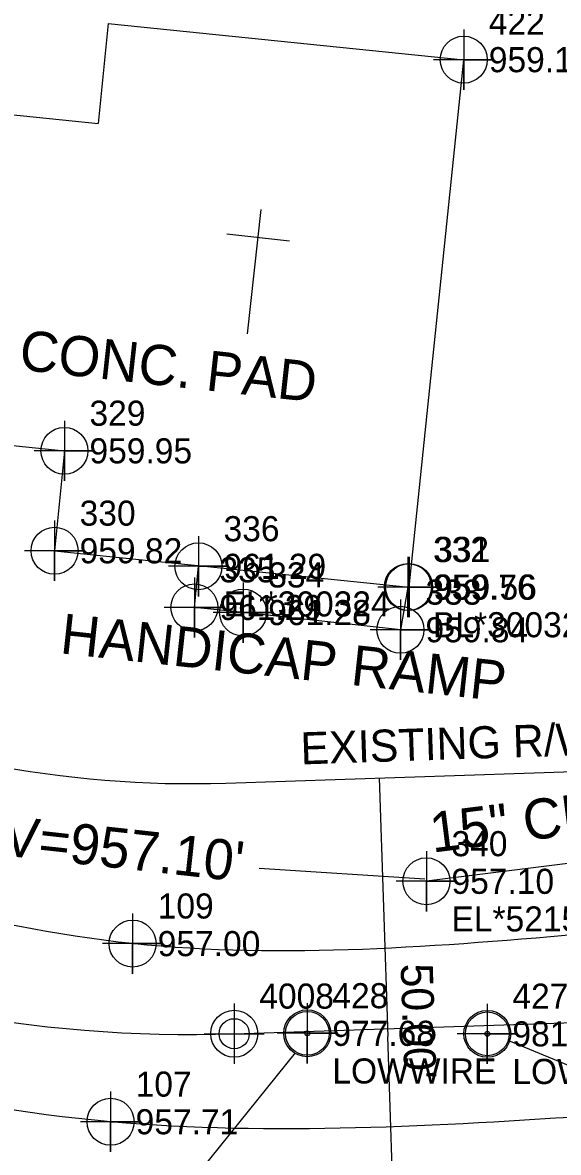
# Model space of a CAD drawing. Extents: x 1150279 to 1151282, y 655434 to 657999.
# Drawn here: x 1150999.3 to 1151052.7, y 657055.2 to 657167.8 of the extents above; entities that cross this region are included whole.
import ezdxf

# ---------------------------------------------------------------- set-up
doc = ezdxf.new("R2010")
doc.units = 0
for name, color, linetype in [('COGO Default Chain', 7, 'Continuous'), ('COGO Default Curve', 7, 'Continuous'), ('Cogo Default Point CELL', 7, 'Continuous'), ('COGO Default Point Number', 7, 'Continuous'), ('Default Symbol CELL', 7, 'Continuous'), ('Default Symbol Cogo Comment', 7, 'Continuous'), ('Default Symbol Cogo Elevation', 7, 'Continuous'), ('Default Symbol Cogo Number', 7, 'Continuous'), ('Exist Building', 7, 'Continuous'), ('Exist Building Cogo Elevation', 7, 'Continuous'), ('Exist Building Cogo Number', 7, 'Continuous'), ('Exist Building Cogo Point CELL', 7, 'Continuous'), ('Exist Horizontal Alignment', 7, 'Continuous'), ('Exist Horizontal Alignment Station Label', 7, 'Continuous'), ('Exist Other Culture Church or Cemetery CELL', 7, 'Continuous'), ('Exist Right of Way Line', 7, 'Continuous'), ('Exist Right of Way Line Text', 7, 'Continuous'), ('Exist Right of Way Width CELL', 7, 'Continuous'), ('Exist Roads EOP', 7, 'Continuous'), ('Exist Roads EOP Cogo Elevation', 7, 'Continuous'), ('Exist Roads EOP Cogo Number', 7, 'Continuous'), ('Exist Roads EOP Cogo Point CELL', 7, 'Continuous'), ('Exist Roads EOP Other', 7, 'Continuous'), ('Exist Roads EOP Other Cogo Comment', 7, 'Continuous'), ('Exist Roads EOP Other Cogo Elevation', 7, 'Continuous'), ('Exist Roads EOP Other Cogo Number', 7, 'Continuous'), ('Exist Roads EOP Other Cogo Point CELL', 7, 'Continuous'), ('Exist Roads EOP Other Text', 7, 'Continuous'), ('Exist Roads EOP Text', 7, 'Continuous'), ('Exist Structure Minor Pipes CMP 15 Inch', 7, 'Continuous'), ('Exist Structure Minor Pipes CMP 15 Inch Cogo Comment', 7, 'Continuous'), ('Exist Structure Minor Pipes CMP 15 Inch Cogo Elevation', 7, 'Continuous'), ('Exist Structure Minor Pipes CMP 15 Inch Cogo Number', 7, 'Continuous'), ('Exist Structure Minor Pipes CMP 15 Inch Cogo Point CELL', 7, 'Continuous'), ('Exist Structure Minor Pipes CMP 15 Inch Leader', 7, 'Continuous'), ('Exist Structure Minor Pipes CMP 15 Inch Text', 7, 'Continuous'), ('Exist Utilities Other Located Object CELL', 7, 'Continuous'), ('Exist Utilities Other Located Object Leader', 7, 'Continuous')]:
    doc.layers.add(name, color=color, linetype=linetype)

msp = doc.modelspace()

# ---------------------------------------------------------------- linework, layer by layer
at = {"layer": 'COGO Default Chain'}
msp.add_line((1151020.37, 657067.07), (1151060.05, 657068.39), dxfattribs=at)
msp.add_arc((1151016.01, 657196.99), 130, 245.6804, 271.9187, dxfattribs=at)
at = {"layer": 'COGO Default Curve'}
msp.add_arc((1151016.01, 657196.99), 130, 245.6804, 271.9187, dxfattribs=at)
at = {"layer": 'Cogo Default Point CELL'}
for points in [[(1151020.37, 657070.07), (1151020.37, 657067.07)], [(1151020.37, 657070.07), (1151020.37, 657067.07)], [(1151017.37, 657067.07), (1151020.37, 657067.07)], [(1151017.37, 657067.07), (1151020.37, 657067.07)], [(1151020.37, 657067.07), (1151023.37, 657067.07)], [(1151020.37, 657067.07), (1151020.37, 657064.07)], [(1151020.37, 657067.07), (1151023.37, 657067.07)], [(1151020.37, 657067.07), (1151020.37, 657064.07)]]:
    msp.add_lwpolyline(points, dxfattribs=at)
msp.add_circle((1151020.37, 657067.07), 2.34, dxfattribs=at)
msp.add_circle((1151020.37, 657067.07), 2.34, dxfattribs=at)
at = {"layer": 'Default Symbol CELL'}
for points in [[(1151027.65, 657070.11), (1151027.65, 657064.11), (1151027.65, 657067.11), (1151030.65, 657067.11), (1151024.65, 657067.11)], [(1151045.59, 657070.06), (1151045.59, 657064.06), (1151045.59, 657067.06), (1151048.59, 657067.06), (1151042.59, 657067.06)]]:
    msp.add_lwpolyline(points, dxfattribs=at)
for centre in [(1151027.65, 657067.11), (1151045.59, 657067.06)]:
    msp.add_circle(centre, 2.34, dxfattribs=at)
at = {"layer": 'Exist Building'}
for p, q in [((1151007.8, 657167.75), (1151006.82, 657157.78)), ((1151007.8, 657167.75), (1151043.24, 657164.12)), ((1150963.17, 657162.3), (1151006.82, 657157.78))]:
    msp.add_line(p, q, dxfattribs=at)
msp.add_lwpolyline([(1150963.17, 657162.3), (1150962, 657151.2), (1150955.74, 657152.17), (1150954.56, 657141.15), (1150960.94, 657140.6), (1150959.8, 657129.69), (1151003.45, 657125.16), (1151002.47, 657115.2), (1151037.8, 657111.58), (1151043.24, 657164.12)], dxfattribs=at)
at = {"layer": 'Exist Building Cogo Point CELL'}
for points in [[(1151043.24, 657167.14), (1151043.24, 657161.14), (1151043.24, 657164.14), (1151046.24, 657164.14), (1151040.24, 657164.14)], [(1151003.45, 657128.16), (1151003.45, 657122.16), (1151003.45, 657125.16), (1151006.45, 657125.16), (1151000.45, 657125.16)], [(1151002.47, 657118.2), (1151002.47, 657112.2), (1151002.47, 657115.2), (1151005.47, 657115.2), (1150999.47, 657115.2)], [(1151037.8, 657114.58), (1151037.8, 657108.58), (1151037.8, 657111.58), (1151040.8, 657111.58), (1151034.8, 657111.58)]]:
    msp.add_lwpolyline(points, dxfattribs=at)
for centre in [(1151043.24, 657164.14), (1151003.45, 657125.16), (1151002.47, 657115.2), (1151037.8, 657111.58)]:
    msp.add_circle(centre, 2.34, dxfattribs=at)
at = {"layer": 'Exist Horizontal Alignment'}
msp.add_line((1151020.37, 657067.07), (1151060.05, 657068.39), dxfattribs=at)
msp.add_arc((1151016.01, 657196.99), 130, 245.6804, 271.9187, dxfattribs=at)
at = {"layer": 'Exist Horizontal Alignment Station Label'}
msp.add_circle((1151020.37, 657067.07), 1.5, dxfattribs=at)
at = {"layer": 'Exist Other Culture Church or Cemetery CELL'}
for p, q in [((1151021.68, 657136.83), (1151023.05, 657149.22)), ((1151019.63, 657146.78), (1151025.87, 657146.09)), ((1151022.37, 657143.04), (1151022.37, 657143.04))]:
    msp.add_line(p, q, dxfattribs=at)
at = {"layer": 'Exist Right of Way Line'}
msp.add_line((1151019.53, 657092.05), (1151059.22, 657093.38), dxfattribs=at)
for radius in [105, 155]:
    msp.add_arc((1151016.01, 657196.99), radius, 245.6804, 271.9187, dxfattribs=at)
at = {"layer": 'Exist Right of Way Width CELL'}
for p in [(1151034.81, 657092.56), (1151036.48, 657042.59)]:
    msp.add_line(p, (1151035.67, 657066.81), dxfattribs=at)
at = {"layer": 'Exist Roads EOP'}
for points in [[(1151056.23, 657077.09), (1151010.25, 657076.05), (1150965.32, 657087.79), (1150920.52, 657109.03), (1150919.16, 657109.82)], [(1151056.97, 657058.93), (1151008.05, 657058.3), (1150957.78, 657070.1), (1150911.09, 657090.11), (1150910.09, 657090.54)]]:
    msp.add_spline(points, degree=3, dxfattribs=at)
at = {"layer": 'Exist Roads EOP Cogo Point CELL'}
for points in [[(1151010.25, 657079.05), (1151010.25, 657073.05), (1151010.25, 657076.05), (1151013.25, 657076.05), (1151007.25, 657076.05)], [(1151008.05, 657061.3), (1151008.05, 657055.3), (1151008.05, 657058.3), (1151011.05, 657058.3), (1151005.05, 657058.3)]]:
    msp.add_lwpolyline(points, dxfattribs=at)
for centre in [(1151010.25, 657076.05), (1151008.05, 657058.3)]:
    msp.add_circle(centre, 2.34, dxfattribs=at)
at = {"layer": 'Exist Roads EOP Other'}
msp.add_lwpolyline([(1151037.68, 657111.58), (1151036.93, 657107.33), (1151021.26, 657109.04), (1151016.4, 657109.55), (1151016.81, 657113.65)], dxfattribs=at)
at = {"layer": 'Exist Roads EOP Other Cogo Point CELL'}
for points in [[(1151016.81, 657116.65), (1151016.81, 657110.65), (1151016.81, 657113.65), (1151019.81, 657113.65), (1151013.81, 657113.65)], [(1151037.68, 657114.58), (1151037.68, 657108.58), (1151037.68, 657111.58), (1151040.68, 657111.58), (1151034.68, 657111.58)], [(1151016.4, 657112.55), (1151016.4, 657106.55), (1151016.4, 657109.55), (1151019.4, 657109.55), (1151013.4, 657109.55)], [(1151021.26, 657112.04), (1151021.26, 657106.04), (1151021.26, 657109.04), (1151024.26, 657109.04), (1151018.26, 657109.04)], [(1151036.93, 657110.33), (1151036.93, 657104.33), (1151036.93, 657107.33), (1151039.93, 657107.33), (1151033.93, 657107.33)]]:
    msp.add_lwpolyline(points, dxfattribs=at)
for centre in [(1151016.81, 657113.65), (1151037.68, 657111.58), (1151016.4, 657109.55), (1151021.26, 657109.04), (1151036.93, 657107.33)]:
    msp.add_circle(centre, 2.34, dxfattribs=at)
at = {"layer": 'Exist Structure Minor Pipes CMP 15 Inch'}
msp.add_line((1151059.72, 657084.82), (1151039.52, 657082.26), dxfattribs=at)
at = {"layer": 'Exist Structure Minor Pipes CMP 15 Inch Cogo Point CELL'}
msp.add_lwpolyline([(1151039.52, 657085.26), (1151039.52, 657079.26), (1151039.52, 657082.26), (1151042.52, 657082.26), (1151036.52, 657082.26)], dxfattribs=at)
msp.add_circle((1151039.52, 657082.26), 2.34, dxfattribs=at)
at = {"layer": 'Exist Structure Minor Pipes CMP 15 Inch Leader'}
msp.add_line((1151039.38, 657082.47), (1151022.85, 657083.53), dxfattribs=at)
at = {"layer": 'Exist Utilities Other Located Object CELL'}
for centre, radius in [((1151027.65, 657067.11), 2.18), ((1151045.59, 657067.06), 2.18), ((1151027.65, 657067.11), 0.24), ((1151045.59, 657067.06), 0.24)]:
    msp.add_circle(centre, radius, dxfattribs=at)
at = {"layer": 'Exist Utilities Other Located Object Leader'}
for points in [[(1151047.69, 657066.38), (1151069.32, 657057.45), (1151082.27, 657056.02)], [(1151026.43, 657065.18), (1151001.23, 657033.86), (1150989.95, 657035.11)]]:
    msp.add_lwpolyline(points, dxfattribs=at)

# ---------------------------------------------------------------- texts
at = {"layer": 'COGO Default Point Number'}
msp.add_text('4008', height=2.5, dxfattribs=at).set_placement((1151022.87, 657069.57))
at = {"layer": 'Default Symbol Cogo Comment'}
for p in [(1151030.15, 657062.11), (1151048.09, 657062.06)]:
    msp.add_text('LOWWIRE', height=2.5, dxfattribs=at).set_placement(p)
at = {"layer": 'Default Symbol Cogo Elevation'}
for s, p in [('977.68', (1151030.15, 657065.86)), ('981.38', (1151048.09, 657065.81))]:
    msp.add_text(s, height=2.5, dxfattribs=at).set_placement(p)
at = {"layer": 'Default Symbol Cogo Number'}
for s, p in [('428', (1151030.15, 657069.61)), ('427', (1151048.09, 657069.56))]:
    msp.add_text(s, height=2.5, dxfattribs=at).set_placement(p)
at = {"layer": 'Exist Building Cogo Elevation'}
for s, p in [('959.11', (1151045.74, 657162.89)), ('959.95', (1151005.95, 657123.91)), ('959.82', (1151004.97, 657113.95)), ('959.56', (1151040.3, 657110.33))]:
    msp.add_text(s, height=2.5, dxfattribs=at).set_placement(p)
at = {"layer": 'Exist Building Cogo Number'}
for s, p in [('422', (1151045.74, 657166.64)), ('329', (1151005.95, 657127.66)), ('330', (1151004.97, 657117.7)), ('331', (1151040.3, 657114.08))]:
    msp.add_text(s, height=2.5, dxfattribs=at).set_placement(p)
at = {"layer": 'Exist Right of Way Line Text'}
msp.add_text('EXISTING R/W', height=3.2, rotation=1.9187, dxfattribs=at).set_placement((1151027.03, 657093.9))
at = {"layer": 'Exist Right of Way Width CELL'}
msp.add_text("50.00'", height=3.2, rotation=271.9187, dxfattribs=at).set_placement((1151036.95, 657074.02))
at = {"layer": 'Exist Roads EOP Cogo Elevation'}
for s, p in [('957.00', (1151012.75, 657074.8)), ('957.71', (1151010.55, 657057.05))]:
    msp.add_text(s, height=2.5, dxfattribs=at).set_placement(p)
at = {"layer": 'Exist Roads EOP Cogo Number'}
for s, p in [('109', (1151012.75, 657078.55)), ('107', (1151010.55, 657060.8))]:
    msp.add_text(s, height=2.5, dxfattribs=at).set_placement(p)
at = {"layer": 'Exist Roads EOP Other Cogo Comment'}
for s, p in [('EL*300324', (1151019.31, 657108.65)), ('BL*300324', (1151040.18, 657106.58))]:
    msp.add_text(s, height=2.5, dxfattribs=at).set_placement(p)
at = {"layer": 'Exist Roads EOP Other Cogo Elevation'}
for s, p in [('961.29', (1151019.31, 657112.4)), ('959.76', (1151040.18, 657110.33)), ('961.29', (1151018.9, 657108.3)), ('961.28', (1151023.76, 657107.79)), ('959.84', (1151039.43, 657106.08))]:
    msp.add_text(s, height=2.5, dxfattribs=at).set_placement(p)
at = {"layer": 'Exist Roads EOP Other Cogo Number'}
for s, p in [('336', (1151019.31, 657116.15)), ('332', (1151040.18, 657114.08)), ('335', (1151018.9, 657112.05)), ('334', (1151023.76, 657111.54)), ('333', (1151039.43, 657109.83))]:
    msp.add_text(s, height=2.5, dxfattribs=at).set_placement(p)
at = {"layer": 'Exist Roads EOP Other Text'}
msp.add_text('HANDICAP RAMP', height=4, rotation=353.7927, dxfattribs=at).set_placement((1151002.93, 657104.99))
at = {"layer": 'Exist Roads EOP Text'}
msp.add_text("6' X 6' CONC. PAD", height=4, rotation=353.6867, dxfattribs=at).set_placement((1150982.92, 657135.02))
at = {"layer": 'Exist Structure Minor Pipes CMP 15 Inch Cogo Comment'}
msp.add_text('EL*521525', height=2.5, dxfattribs=at).set_placement((1151042.02, 657077.26))
at = {"layer": 'Exist Structure Minor Pipes CMP 15 Inch Cogo Elevation'}
msp.add_text('957.10', height=2.5, dxfattribs=at).set_placement((1151042.02, 657081.01))
at = {"layer": 'Exist Structure Minor Pipes CMP 15 Inch Cogo Number'}
msp.add_text('340', height=2.5, dxfattribs=at).set_placement((1151042.02, 657084.76))
at = {"layer": 'Exist Structure Minor Pipes CMP 15 Inch Text'}
for s, rotation, p in [('15" CMP', 7.2171, (1151040.13, 657085.11)), ("INV=957.10'", 353.6867, (1150991.87, 657085.44))]:
    msp.add_text(s, height=4, rotation=rotation, dxfattribs=at).set_placement(p)

doc.saveas('drawing.dxf')
